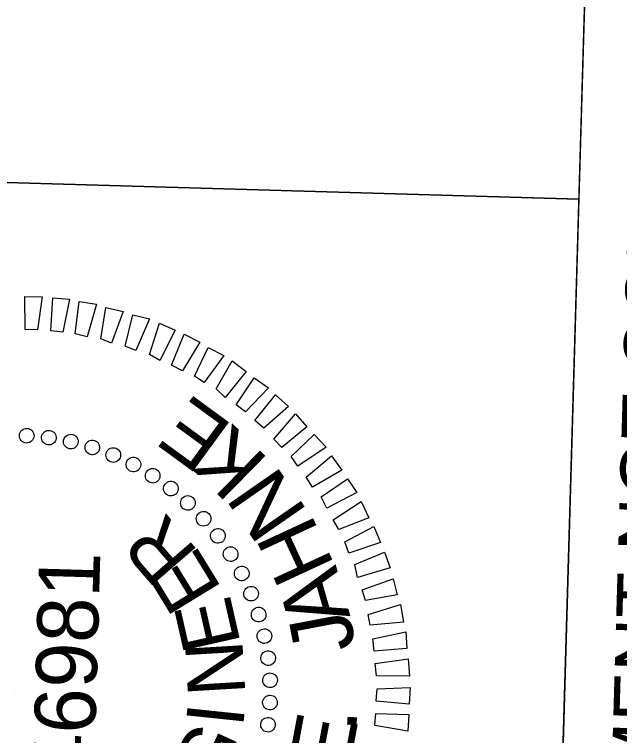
# Model space of a CAD drawing. Extents: x 2097422 to 2097881, y 685612 to 686386.
# Drawn here: x 2097482.75 to 2097506.52, y 686228.48 to 686256.82 of the extents above; entities that cross this region are included whole.
import ezdxf

# ---------------------------------------------------------------- set-up
doc = ezdxf.new("R2010")
doc.units = 0
for name, color, linetype in [('Sheet PE Seal Cell', 7, 'Continuous'), ('Sheet Profile CELL', 7, 'Continuous'), ('Sheet Sticker Exception Certification CELL', 7, 'Continuous')]:
    doc.layers.add(name, color=color, linetype=linetype)

msp = doc.modelspace()

# ---------------------------------------------------------------- linework, layer by layer
at = {"layer": 'Sheet PE Seal Cell'}
for p, q in [((2097483.238, 686240.277), (2097483.238, 686240.277)), ((2097484.116, 686240.191), (2097484.116, 686240.191)), ((2097484.971, 686240.026), (2097484.971, 686240.026)), ((2097485.806, 686239.822), (2097485.806, 686239.822)), ((2097486.637, 686239.518), (2097486.637, 686239.518)), ((2097487.426, 686239.135), (2097487.426, 686239.135)), ((2097488.194, 686238.712), (2097488.194, 686238.712)), ((2097488.9, 686238.191), (2097488.9, 686238.191)), ((2097489.584, 686237.631), (2097489.584, 686237.631)), ((2097490.186, 686237.014), (2097490.186, 686237.014)), ((2097490.767, 686236.336), (2097490.767, 686236.336)), ((2097491.246, 686235.622), (2097491.246, 686235.622)), ((2097491.684, 686234.849), (2097491.684, 686234.849)), ((2097492.061, 686234.058), (2097492.061, 686234.058)), ((2097492.357, 686233.249), (2097492.357, 686233.249)), ((2097492.573, 686232.402), (2097492.573, 686232.402)), ((2097492.707, 686231.518), (2097492.707, 686231.518)), ((2097492.802, 686230.655), (2097492.802, 686230.655)), ((2097482.766, 686230.246), (2097482.766, 686230.246)), ((2097492.797, 686229.775), (2097492.797, 686229.775)), ((2097492.711, 686228.897), (2097492.711, 686228.897))]:
    msp.add_line(p, q, dxfattribs=at)
for points in [[(2097483.179, 686244.44), (2097483.157, 686245.742), (2097483.836, 686245.722), (2097483.659, 686244.426)], [(2097484.178, 686244.391), (2097484.256, 686245.69), (2097484.914, 686245.63), (2097484.656, 686244.337)], [(2097485.135, 686244.263), (2097485.292, 686245.539), (2097485.969, 686245.44), (2097485.611, 686244.15)], [(2097486.149, 686244.074), (2097486.345, 686245.309), (2097487.021, 686245.149), (2097486.565, 686243.902)], [(2097487.101, 686243.786), (2097487.397, 686245.018), (2097488.053, 686244.859), (2097487.517, 686243.614)], [(2097488.052, 686243.458), (2097488.448, 686244.687), (2097489.06, 686244.409), (2097488.466, 686243.226)], [(2097488.92, 686243.033), (2097489.416, 686244.259), (2097490.027, 686243.941), (2097489.354, 686242.82)], [(2097489.828, 686242.606), (2097490.361, 686243.731), (2097490.972, 686243.413), (2097490.201, 686242.355)], [(2097490.674, 686242.102), (2097491.306, 686243.204), (2097491.854, 686242.788), (2097491.025, 686241.771)], [(2097491.456, 686241.479), (2097492.167, 686242.538), (2097492.736, 686242.142), (2097491.829, 686241.208)], [(2097492.199, 686240.857), (2097493.008, 686241.874), (2097493.515, 686241.419), (2097492.55, 686240.566)], [(2097492.938, 686240.135), (2097493.787, 686241.131), (2097494.232, 686240.618), (2097493.248, 686239.806)], [(2097493.618, 686239.455), (2097494.524, 686240.309), (2097494.989, 686239.815), (2097493.887, 686239.067)], [(2097494.215, 686238.637), (2097495.199, 686239.469), (2097495.604, 686238.917), (2097494.464, 686238.25)], [(2097494.793, 686237.86), (2097495.834, 686238.57), (2097496.198, 686238.039), (2097495.02, 686237.413)], [(2097495.267, 686236.966), (2097496.368, 686237.674), (2097496.67, 686237.045), (2097495.496, 686236.579)], [(2097495.722, 686236.092), (2097496.86, 686236.7), (2097497.122, 686236.072), (2097495.889, 686235.647)], [(2097496.116, 686235.201), (2097497.29, 686235.687), (2097497.513, 686235.08), (2097496.221, 686234.697)], [(2097496.407, 686234.212), (2097497.62, 686234.637), (2097497.782, 686234.012), (2097496.535, 686233.788)], [(2097496.639, 686233.244), (2097497.911, 686233.628), (2097498.031, 686232.944), (2097496.727, 686232.822)], [(2097496.831, 686232.278), (2097498.12, 686232.561), (2097498.161, 686231.9), (2097496.877, 686231.797)], [(2097496.923, 686231.315), (2097498.209, 686231.498), (2097498.269, 686230.816), (2097496.969, 686230.834)], [(2097496.994, 686230.313), (2097498.296, 686230.375), (2097498.257, 686229.716), (2097496.96, 686229.834)], [(2097496.946, 686229.354), (2097498.246, 686229.316), (2097498.207, 686228.657), (2097496.912, 686228.875)]]:
    msp.add_lwpolyline(points, close=True, dxfattribs=at)
for centre, major_axis in [((2097483.233, 686240.267), (0.013, 0.288)), ((2097484.104, 686240.189), (0.038, 0.285)), ((2097484.966, 686240.034), (0.063, 0.281)), ((2097485.81, 686239.805), (0.087, 0.274)), ((2097486.632, 686239.504), (0.111, 0.266)), ((2097487.424, 686239.131), (0.134, 0.255)), ((2097488.181, 686238.692), (0.155, 0.242)), ((2097488.896, 686238.188), (0.176, 0.228)), ((2097489.565, 686237.623), (0.195, 0.212)), ((2097490.182, 686237.003), (0.213, 0.194)), ((2097490.743, 686236.33), (0.229, 0.175)), ((2097491.243, 686235.612), (0.243, 0.154)), ((2097491.678, 686234.853), (0.256, 0.132)), ((2097492.046, 686234.059), (0.266, 0.109)), ((2097492.343, 686233.235), (0.275, 0.086)), ((2097492.567, 686232.389), (0.281, 0.062)), ((2097492.716, 686231.527), (0.286, 0.037)), ((2097492.79, 686230.655), (0.288, 0.012)), ((2097492.787, 686229.78), (0.288, -0.013)), ((2097492.709, 686228.908), (0.285, -0.038))]:
    msp.add_ellipse(centre, major_axis=major_axis, ratio=0.999708, dxfattribs=at)
at = {"layer": 'Sheet Profile CELL'}
msp.add_line((2097459.941, 686250.87), (2097504.902, 686249.563), dxfattribs=at)
for points in [[(2097459.941, 686250.87), (2097461.103, 686290.853), (2097506.084, 686289.546), (2097504.922, 686249.563)], [(2097458.778, 686210.867), (2097459.941, 686250.87), (2097504.922, 686249.563), (2097503.759, 686209.559)]]:
    msp.add_lwpolyline(points, close=True, dxfattribs=at)
at = {"layer": 'Sheet Sticker Exception Certification CELL'}
msp.add_line((2097503.759, 686209.559), (2097506.084, 686289.541), dxfattribs=at)

# ---------------------------------------------------------------- texts
at = {"layer": 'Sheet PE Seal Cell'}
for s, height, rotation, p in [('E', 2.399, 143.8279, (2097491.389, 686240.641)), ('K', 2.399, 135.5439, (2097492.796, 686239.29)), ('N', 2.399, 124.8181, (2097494.304, 686237.266)), ('R', 2.256, 130.8162, (2097490.027, 686235.678)), ('H', 2.399, 114.8341, (2097495.347, 686235.159)), ('E', 2.255, 121.4589, (2097490.925, 686234.231)), ('046981', 2.3993, 88.3348, (2097485.817, 686224.967)), ('A', 2.399, 105.9938, (2097495.952, 686233.167)), ('E', 2.255, 102.7466, (2097491.643, 686232.089)), ('J', 2.399, 100.736, (2097496.164, 686231.947)), ('N', 2.255, 93.3912, (2097491.826, 686230.103)), ('I', 2.255, 84.036, (2097491.727, 686228.765)), ('E', 2.399, 79.3925, (2097495.864, 686226.954)), ('.', 2.399, 86.5019, (2097496.171, 686228.6)), ('G', 2.255, 65.3251, (2097490.891, 686226.169))]:
    msp.add_text(s, height=height, rotation=rotation, dxfattribs=at).set_placement(p)
at = {"layer": 'Sheet Sticker Exception Certification CELL'}
msp.add_text('DOCUMENT NOT CONSIDERED FINAL', height=2.2, rotation=88.3348, dxfattribs=at).set_placement((2097508.141, 686217.864))

doc.saveas('drawing.dxf')
